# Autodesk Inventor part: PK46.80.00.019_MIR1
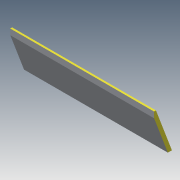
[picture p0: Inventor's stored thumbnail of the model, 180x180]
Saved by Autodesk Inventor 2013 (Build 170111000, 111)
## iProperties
Created: 2005-01
Part Number: PK46.80.00.019_MIR1
Material: Steel, Mild
Document SubType Name: Modeling
Designer: hoeyj
Manufacturer: Standard
Standards Organization: Custom
Density: 7.86 g/cm^3
Mass: 12177.1 g
Surface Area: 1953.57 cm^2
Volume: 1549.25 cm^3
Author: SAlex
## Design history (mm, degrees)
derived "PK46.80.00.019.ipt"
body "Solid1"
tag "TaggingFeature2"
feature "DerivedBody::PK46.80.00.019.ipt" dims "d0" = 10
